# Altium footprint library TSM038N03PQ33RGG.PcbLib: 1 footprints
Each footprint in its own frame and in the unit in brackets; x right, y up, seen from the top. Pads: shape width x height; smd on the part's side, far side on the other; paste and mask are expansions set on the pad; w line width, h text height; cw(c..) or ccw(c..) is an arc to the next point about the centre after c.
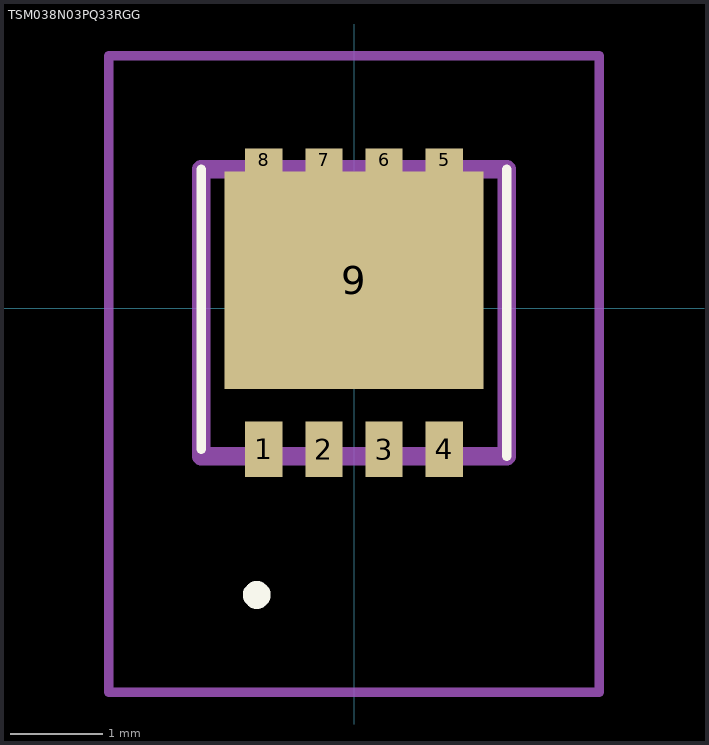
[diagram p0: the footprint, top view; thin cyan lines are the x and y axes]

## TSM038N03PQ33RGG [mm]
pads (9):
  rect 0.4x0.6 smd: 1(-0.975,-1.525) 2(-0.325,-1.525) 3(0.325,-1.525) 4(0.975,-1.525)
  rect 0.4x0.25 smd: 5(0.975,1.6) 6(0.325,1.6) 7(-0.325,1.6) 8(-0.975,1.6)
  rect 2.8x2.35 smd: 9(0,0.3)
Top Overlay:
  lines w0.1: -1.65,-1.525 -1.65,1.5 ; -1.65,-1.525 -1.65,-1.525 ; -1.65,-1.525 -1.65,1.5 ; -1.65,1.5 -1.65,1.5 ; 1.65,-1.6 1.65,1.5 ; 1.65,-1.6 1.65,-1.6 ; 1.65,-1.6 1.65,1.5 ; 1.65,1.5 1.65,1.5
  lines w0.2: -1.1,-3.1 -1.1,-3.1 ; -1.1,-3.1 ccw(c-1.05,-3.1) -1,-3.1 ; -1.1,-3.1 cw(c-1.05,-3.1) -1,-3.1 ; -1.1,-3.1 -1.1,-3.1 ; -1.1,-3.1 ccw(c-1.05,-3.1) -1,-3.1 ; -1,-3.1 -1,-3.1
Mechanical 15:
  lines w0.2: -1.65,-1.6 1.65,-1.6 1.65,1.5 -1.65,1.5 -1.65,-1.6
Mechanical 20:
  lines w0.1: -2.65,-4.15 2.65,-4.15 2.65,2.725 -2.65,2.725 -2.65,-4.15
